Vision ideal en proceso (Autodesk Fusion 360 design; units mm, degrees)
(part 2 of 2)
sketch "Sketch1" plane through (0, 0, 0) normal (0, 0, 1) x axis (1, 0, 0)
  line L1 (412, 0) -> (0, 0)
  line L2 (412, 555) -> (412, 0)
  line L3 (0, 555) -> (412, 555)
  line L4 (0, 0) -> (0, 555)
  circle C1 centre (30, 465) radius 10
  circle C2 centre (30, 415) radius 10
  circle C3 centre (30, 365) radius 10
  circle C4 centre (30, 315) radius 10
  circle C5 centre (30, 265) radius 10
  circle C6 centre (30, 215) radius 10
  circle C7 centre (30, 165) radius 10
  circle C8 centre (30, 115) radius 10
  point P1 (0, 0)
  point P2 (0, 0)
  point P5 (0, 555)
  point P3 (412, 0)
  point P6 (30, 465)
  point P7 (30, 415)
  point P8 (30, 365)
  point P9 (30, 315)
  point P10 (30, 265)
  point P11 (30, 215)
  point P12 (30, 165)
  point P13 (30, 115)
  horizontal L1
  vertical L2
  horizontal L3
  vertical L4
  coincident P1 P2
  dimension "d1_1" distance P2 P5 = 555
  dimension "d2_1" distance P2 P3 = 412
  dimension "d3_1" diameter C1 = 20
  dimension "d4_1" distance L4 P6 = 30
  dimension "d5_1" distance L3 P6 = 90
  dimension "d6_1" diameter C2 = 20
  dimension "d7" distance P6 P7 = 50
  dimension "d8_1" diameter C3 = 20
  dimension "d9_1" diameter C4 = 20
  dimension "d10_1" diameter C5 = 20
  dimension "d11_1" distance P7 P8 = 50
  dimension "d12_1" distance P8 P9 = 50
  dimension "d13_1" distance P9 P10 = 50
  dimension "d14_1" diameter C6 = 20
  dimension "d15_1" diameter C7 = 20
  dimension "d16_1" diameter C8 = 20
  dimension "d17_1" distance P10 P11 = 50
  dimension "d18_1" distance P11 P12 = 50
  dimension "d19_1" distance P12 P13 = 50
extrude "Extrude1" new body sketch "Sketch1" along normal blind 10 named "d20_1"
sketch "Sketch1" plane through (0, 0, 0) normal (0, 0, 1) x axis (1, 0, 0)
  line L1 (370, 15) -> (0, 15)
  line L2 (370, 13) -> (370, 15)
  line L3 (0, 13) -> (370, 13)
  line L4 (0, 15) -> (0, 13)
  circle C1 centre (0, 0) radius 10
  circle C2 centre (0, 0) radius 15
  point P1 (0, 0)
  point P2 (0, 0)
  point P3 (0, 0)
  point P4 (0, 15)
  point P7 (0, 13)
  point P5 (370, 15)
  coincident P1 P2
  coincident P1 P3
  horizontal L1
  vertical L2
  horizontal L3
  vertical L4
  coincident C2 P4
  dimension "d1_7" diameter C1 = 20
  dimension "d2_7" diameter C2 = 30
  dimension "d3_7" distance P4 P7 = 2
  dimension "d4_7" distance P4 P5 = 370
extrude "Extrude1" new body sketch "Sketch1" along normal blind 380 named "d5_7"
extrude "Extrude2" add sketch "Sketch1" profile of C1 against normal blind 10 named "d7_6"
sketch "Sketch2" plane through (0, 0, 380) normal (0, 0, 1) x axis (-1, 0, 0)
  line L1 (-370, -13) -> (-7.4833, -13)
  line L2 (-370, -15) -> (-370, -13)
  line L3 (0, -15) -> (-370, -15)
  arc A1 centre (0, 0) radius 15 clockwise from (-7.4833, -13) to (0, -15)
  circle C1 centre (0, 0) radius 10
  concentric A1 C1
  dimension "d9_7" diameter C1 = 20
extrude "Extrude3" add sketch "Sketch2" profile of C1 along normal blind 10 named "d10_6"
sketch "Sketch1" plane through (0, 0, 0) normal (0, 1, 0) x axis (1, 0, 0)
  circle C1 centre (0, 0) radius 10
  circle C2 centre (0, 0) radius 15
  point P1 (0, 0)
  point P2 (0, 0)
  point P3 (0, 0)
  coincident P1 P2
  coincident P1 P3
  dimension "d1_8" diameter C1 = 20
  dimension "d2_8" diameter C2 = 30
extrude "Extrude1" new body sketch "Sketch1" along normal blind 380 named "d3_8"
extrude "Extrude2" add sketch "Sketch1" profile of C1 against normal blind 10 named "d5_8"
sketch "Sketch2" plane through (0, 380, 0) normal (0, 1, 0) x axis (-1, 0, 0)
  circle C1 centre (0, 0) radius 15
  circle C2 centre (0, 0) radius 10
  concentric C1 C2
  dimension "d7_7" diameter C2 = 20
extrude "Extrude3" add sketch "Sketch2" profile of C2 along normal blind 10 named "d8_8"
sketch "Sketch1" plane through (0, 0, 0) normal (0, 1, 0) x axis (1, 0, 0)
  circle C1 centre (0, 0) radius 10
  circle C2 centre (0, 0) radius 15
  point P1 (0, 0)
  point P2 (0, 0)
  point P3 (0, 0)
  coincident P1 P2
  coincident P1 P3
  dimension "d1_9" diameter C1 = 20
  dimension "d2_9" diameter C2 = 30
extrude "Extrude1" new body sketch "Sketch1" along normal blind 380 named "d3_9"
extrude "Extrude2" add sketch "Sketch1" profile of C1 against normal blind 10 named "d5_9"
sketch "Sketch2" plane through (0, 380, 0) normal (0, 1, 0) x axis (-1, 0, 0)
  circle C1 centre (0, 0) radius 15
  circle C2 centre (0, 0) radius 10
  concentric C1 C2
  dimension "d7_8" diameter C2 = 20
extrude "Extrude3" add sketch "Sketch2" profile of C2 along normal blind 10 named "d8_9"
copy_paste_bodies "CopyPasteBodies1"
move "Move1"
move "Move2"
position "Position2"
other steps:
base_feature "Base Feature"
create_component "CreateComponent1"
create_component "CreateComponent2"
create_component "CreateComponent3"
create_component "CreateComponent4"
create_component "CreateComponent5"
create_component "CreateComponent6"
create_component "CreateComponent1"
create_component "CreateComponent2"
create_component "CreateComponent3"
